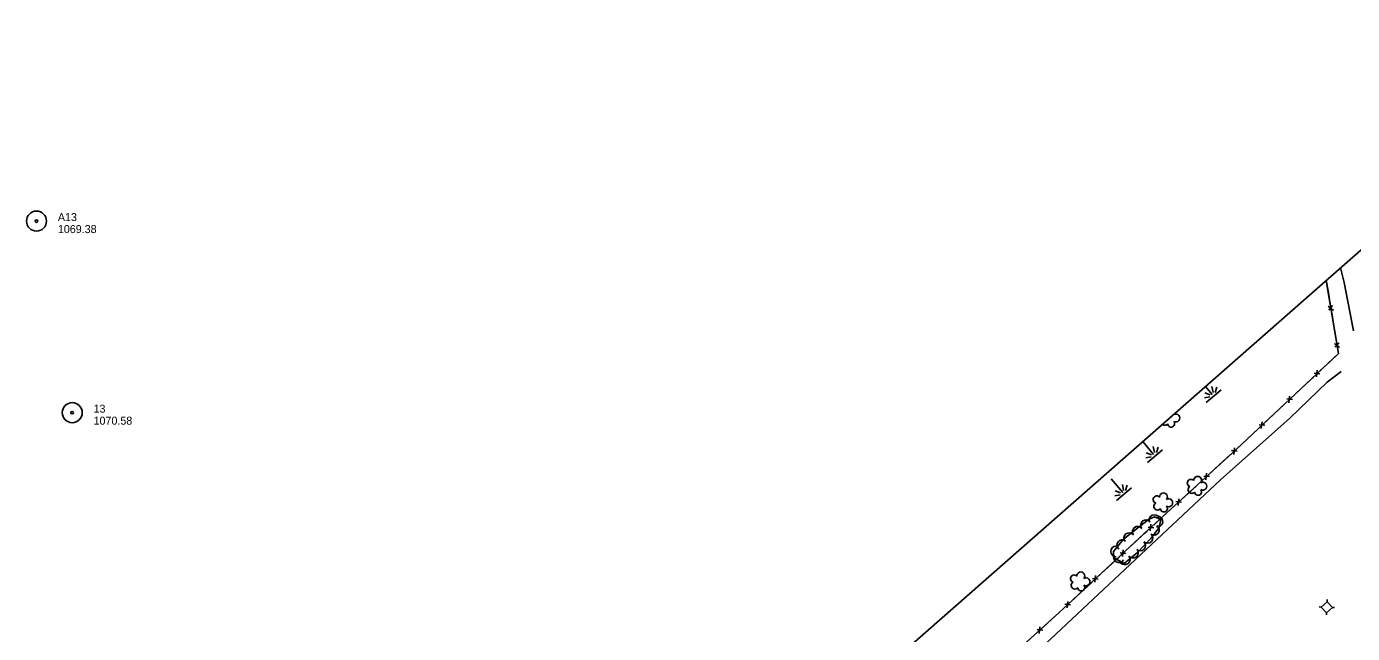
# Model space of a CAD drawing. Extents: x 295302 to 297577, y 27143 to 29590.
# Drawn here: x 295302 to 296296, y 28582 to 29036 of the extents above; entities that cross this region are included whole.
import ezdxf

# ---------------------------------------------------------------- set-up
doc = ezdxf.new("R2010")
doc.units = 0
for name, color, linetype in [('Level 11', 7, 'Continuous'), ('Level 15', 7, 'Continuous'), ('Level 17', 7, 'Continuous'), ('Level 18', 7, 'Continuous'), ('Level 19', 7, 'Continuous'), ('Level 21', 7, 'Continuous'), ('Level 4', 7, 'Continuous'), ('Level 6', 7, 'Continuous')]:
    doc.layers.add(name, color=color, linetype=linetype)

msp = doc.modelspace()

# ---------------------------------------------------------------- linework, layer by layer
at = {"layer": 'Level 11'}
msp.add_lwpolyline([(296296.5, 28808.21), (296289.55, 28844.57), (296286.84, 28855.43)], dxfattribs=at)
at = {"layer": 'Level 15'}
for p, q in [((296277.6, 28826.83), (296281.47, 28823.65)), ((296280.88, 28827.21), (296278.17, 28823.87)), ((296282.27, 28798.91), (296286.14, 28795.73)), ((296285.54, 28799.28), (296282.83, 28795.95)), ((296271.44, 28776.19), (296267.17, 28776.61)), ((296269.32, 28778.72), (296268.81, 28773.73)), ((296250.77, 28756.85), (296246.49, 28757.26)), ((296248.65, 28759.37), (296248.14, 28754.39)), ((296230.1, 28737.51), (296225.82, 28737.92)), ((296227.98, 28740.03), (296227.47, 28735.05)), ((296209.41, 28718.16), (296205.14, 28718.62)), ((296207.31, 28720.71), (296206.75, 28715.73)), ((296188.54, 28699.03), (296184.27, 28699.49)), ((296186.45, 28701.57), (296185.89, 28696.6)), ((296167.68, 28679.9), (296163.41, 28680.35)), ((296165.58, 28682.44), (296165.02, 28677.46)), ((296146.81, 28660.77), (296142.54, 28661.22)), ((296144.71, 28663.31), (296144.16, 28658.33)), ((296126.02, 28641.56), (296121.75, 28641.99)), ((296123.91, 28644.09), (296123.38, 28639.11)), ((296103.15, 28624.85), (296102.62, 28619.87)), ((296105.26, 28622.32), (296100.99, 28622.75)), ((296082.39, 28605.6), (296081.85, 28600.62)), ((296084.5, 28603.07), (296080.22, 28603.51)), ((296061.51, 28586.52), (296060.92, 28581.54)), ((296063.59, 28583.96), (296059.32, 28584.44))]:
    msp.add_line(p, q, dxfattribs=at)
for points in [[(296276.18, 28846.07), (296285.34, 28791.28), (296208.62, 28719.5), (296139.52, 28656.15), (296075.6, 28596.91), (296001.45, 28529.71), (295938.47, 28471.89), (295884.83, 28422.36), (295819.8, 28364.6), (295769.53, 28318.85), (295750.14, 28301.92), (295710.44, 28274.72)], [(296276.18, 28846.07), (296277.49, 28838.27)], [(296277.49, 28838.27), (296279.15, 28828.29)], [(296280.26, 28821.69), (296282.15, 28810.34)], [(296282.15, 28810.34), (296283.82, 28800.36)], [(296284.92, 28793.77), (296285.34, 28791.28), (296278.78, 28785.14)], [(296278.78, 28785.14), (296271.39, 28778.23)], [(296258.1, 28765.8), (296250.72, 28758.89)], [(296266.51, 28773.66), (296258.1, 28765.8)], [(296245.83, 28754.32), (296237.43, 28746.46)], [(296237.43, 28746.46), (296230.04, 28739.55)], [(296225.16, 28734.98), (296216.76, 28727.12)], [(296216.76, 28727.12), (296209.37, 28720.21)], [(296204.45, 28715.68), (296195.97, 28707.9)], [(296195.97, 28707.9), (296188.51, 28701.07)], [(296183.58, 28696.55), (296175.1, 28688.77)], [(296175.1, 28688.77), (296167.64, 28681.94)], [(296162.71, 28677.42), (296154.23, 28669.64)], [(296154.23, 28669.64), (296146.78, 28662.8)], [(296141.85, 28658.28), (296139.52, 28656.15), (296133.4, 28650.48)], [(296133.4, 28650.48), (296125.98, 28643.6)], [(296121.07, 28639.05), (296112.64, 28631.23)], [(296112.64, 28631.23), (296105.22, 28624.35)], [(296100.31, 28619.81), (296091.87, 28611.99)], [(296091.87, 28611.99), (296084.45, 28605.11)], [(296079.55, 28600.56), (296075.6, 28596.91), (296071.06, 28592.8)], [(296071.06, 28592.8), (296063.57, 28586)]]:
    msp.add_lwpolyline(points, dxfattribs=at)
at = {"layer": 'Level 17'}
msp.add_lwpolyline([(295769.8, 28306.78), (295832.14, 28364.62), (295878.58, 28406.02), (295925.45, 28449.27), (295976.52, 28494.41), (296049.61, 28558.68), (296125.2, 28629.4), (296196.94, 28696.67), (296248.89, 28742.92), (296276.75, 28769.94), (296287.3, 28777.73)], dxfattribs=at)
at = {"layer": 'Level 18'}
msp.add_lwpolyline([(296124.04, 28652.17), (296116.54, 28643.02), (296116.67, 28638.41), (296124.66, 28634.03), (296134.67, 28642.09), (296144.92, 28653.03), (296150.95, 28660.87), (296152.02, 28666.96), (296147.36, 28668.85), (296143.02, 28666.84), (296124.04, 28652.17)], dxfattribs=at)
for centre, radius, start, end in [((296159.54, 28747.41), 2.97, 320.93961, 329.89047), ((296163.41, 28743.02), 2.97, 238.59043, 121.5637), ((296155.11, 28740.34), 2.78, 230.10512, 321.59856), ((296159.89, 28738.76), 2.61, 183.29566, 41.22827), ((296174.75, 28694.26), 2.78, 43.91051, 251.6835), ((296179.73, 28696.3), 2.97, 320.93961, 182.1735), ((296183.6, 28691.91), 2.97, 238.59043, 121.5637), ((296149.17, 28681.82), 2.78, 43.91051, 251.6835), ((296154.15, 28683.86), 2.97, 320.93961, 182.1735), ((296175.3, 28689.23), 2.78, 120.58752, 321.59856), ((296180.09, 28687.65), 2.61, 183.29566, 41.22827), ((296149.72, 28676.79), 2.78, 120.58752, 321.59856), ((296154.5, 28675.21), 2.61, 183.29566, 41.22827), ((296158.02, 28679.47), 2.97, 238.59043, 121.5637), ((296141.03, 28662.67), 3.97, 37.70792, 217.69259), ((296147.36, 28666.55), 3.97, 24.78866, 204.77334), ((296149.63, 28665.4), 3.97, 260.03621, 80.02088), ((296128.46, 28652.96), 3.97, 37.70792, 217.69259), ((296134.74, 28657.81), 3.97, 37.70792, 217.69259), ((296142.2, 28653.16), 3.97, 226.84534, 46.83002), ((296147.04, 28659.19), 3.97, 232.4705, 52.45518), ((296118.62, 28643), 3.97, 91.64921, 271.63389), ((296123.13, 28647.78), 3.97, 50.66205, 230.64673), ((296131.29, 28642.04), 3.97, 218.88746, 38.87214), ((296136.76, 28647.37), 3.97, 226.84534, 46.83002), ((296120.67, 28638.59), 3.97, 151.2211, 331.20578), ((296125.1, 28637.05), 3.97, 218.88746, 38.87214), ((296087.18, 28622.61), 2.78, 43.91051, 251.6835), ((296092.15, 28624.65), 2.97, 320.93961, 182.1735), ((296087.72, 28617.58), 2.78, 120.58752, 321.59856), ((296092.51, 28616), 2.61, 183.29566, 41.22827), ((296096.03, 28620.26), 2.97, 238.59043, 121.5637)]:
    msp.add_arc(centre, radius, start, end, dxfattribs=at)
at = {"layer": 'Level 19'}
for p, q in [((296185.66, 28766.6), (296190.73, 28760.68)), ((296186.15, 28754.6), (296197.4, 28764.21)), ((296191.31, 28762.19), (296190.48, 28766.55)), ((296194.2, 28766.18), (296192.76, 28762.19)), ((296184.79, 28758.14), (296188.95, 28758.94)), ((296189.18, 28760.37), (296185.01, 28761.87)), ((296138.59, 28725.27), (296146.77, 28715.71)), ((296145.22, 28715.4), (296141.05, 28716.9)), ((296142.19, 28709.63), (296153.44, 28719.24)), ((296147.35, 28717.22), (296146.52, 28721.58)), ((296150.24, 28721.21), (296148.8, 28717.23)), ((296140.83, 28713.17), (296144.99, 28713.98)), ((296114.82, 28697.44), (296123.54, 28687.24)), ((296117.6, 28684.7), (296121.76, 28685.51)), ((296121.99, 28686.93), (296117.82, 28688.43)), ((296118.96, 28681.16), (296130.21, 28690.78)), ((296124.12, 28688.76), (296123.29, 28693.11)), ((296127.01, 28692.74), (296125.57, 28688.76))]:
    msp.add_line(p, q, dxfattribs=at)
at = {"layer": 'Level 21'}
for p, q in [((296276.7, 28605.36), (296276.77, 28606.86)), ((296272.28, 28601.31), (296270.78, 28601.37)), ((296276.27, 28595.39), (296276.33, 28596.89)), ((296282.25, 28600.88), (296280.75, 28600.94))]:
    msp.add_line(p, q, dxfattribs=at)
msp.add_lwpolyline([(296276.33, 28596.89), (296280.75, 28600.94), (296276.7, 28605.36), (296272.28, 28601.31)], close=True, dxfattribs=at)
at = {"layer": 'Level 4'}
msp.add_lwpolyline([(295725.55, 28362.64), (296492.89, 29036.34)], dxfattribs=at)
at = {"layer": 'Level 6'}
for centre, radius in [((295309.39, 28890.55), 7.5), ((295309.39, 28890.55), 0.96), ((295336.15, 28746.99), 7.5), ((295336.15, 28746.99), 0.96)]:
    msp.add_circle(centre, radius, dxfattribs=at)

# ---------------------------------------------------------------- texts
for s, p in [('A13', (295325.39, 28890.55)), ('1069.38', (295325.39, 28881.55)), ('13', (295352.15, 28746.99)), ('1070.58', (295352.15, 28737.99))]:
    msp.add_text(s, height=6, dxfattribs=at).set_placement(p)

doc.saveas('drawing.dxf')
